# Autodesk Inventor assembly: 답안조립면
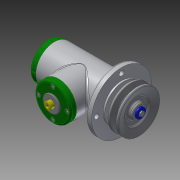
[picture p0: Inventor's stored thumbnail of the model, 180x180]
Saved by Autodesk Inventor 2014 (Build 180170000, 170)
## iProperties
Created: 2016-08
Part Number: 답안조립면
Document SubType Name: Assembly
Designer: user
Author: user
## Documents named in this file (25)
- C:\Users\user\Desktop\460808V1015\답안조립품.iam
- C:\Users\user\Desktop\460808V1015\본체.ipt
- C:\Users\user\Desktop\460808V1015\사이드 커버.ipt
- 사이드 커버.ipt
- C:\Users\user\Desktop\460808V1015\베어링 15 x 35 x 11.ipt
- C:\Users\user\Desktop\460808V1015\오일 실 15 25 7.ipt
- C:\Users\user\Desktop\460808V1015\편심축.ipt
- C:\Users\user\Desktop\460808V1015\탑 커버.ipt
- 탑 커버.ipt
- C:\Users\user\Desktop\460808V1015\탑 부시.ipt
- C:\Users\user\Desktop\460808V1015\V-벨트풀리.ipt
- C:\Users\user\Desktop\460808V1015\키 4 x 4 x 18.ipt
- C:\Users\user\Desktop\460808V1015\와셔 4x16.ipt
- C:\Users\user\Desktop\460808V1015\볼트 M4 x 10.ipt
- C:\Users\user\Desktop\460808V1015\멈춤링 35x1.6.ipt
- C:\Users\user\Desktop\460808V1015\멈춤링 15 x 1.ipt
- C:\Users\user\Desktop\460808V1015\부시2.ipt
- C:\Users\user\Desktop\460808V1015\와셔 10x21.ipt
- C:\Users\user\Desktop\460808V1015\너트 M10.ipt
- C:\Users\user\Desktop\460808V1015\볼트 M4 x 12.ipt
- C:\Users\user\Desktop\460808V1015\슬라이더.ipt
- C:\Users\user\Desktop\460808V1015\분할핀 1.6 x 12.ipt
- C:\Users\user\Desktop\460808V1015\클래스터 핀 6 x 24.ipt
- C:\Users\user\Desktop\460808V1015\부시1.ipt
- C:\Users\user\Desktop\460808V1015\링크.ipt
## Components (6 placed, 3 different names)
1. V-벨트풀리:1 — Angle:2, Insert:8, Insert:9
2. ISO 4017 M4 x 10:1 — Rigid:1
3. ISO 4762 M4 x 12:1 — Rigid:3
4. ISO 4762 M4 x 12:2 — Rigid:4
5. ISO 4762 M4 x 12:3 — Rigid:6, Angle:7
6. ISO 4762 M4 x 12:4 — Rigid:5
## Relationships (9: WeldJoint 5, Angle 2, Insert 2)
- Angle:2: V-벨트풀리:1
- Insert:8: V-벨트풀리:1
- Insert:9: V-벨트풀리:1
- Rigid:1 [WeldJoint]: ISO 4017 M4 x 10:1
- Rigid:3 [WeldJoint]: ISO 4762 M4 x 12:1
- Rigid:4 [WeldJoint]: ISO 4762 M4 x 12:2
- Rigid:5 [WeldJoint]: ISO 4762 M4 x 12:4
- Rigid:6 [WeldJoint]: ISO 4762 M4 x 12:3
- Angle:7: ISO 4762 M4 x 12:3
